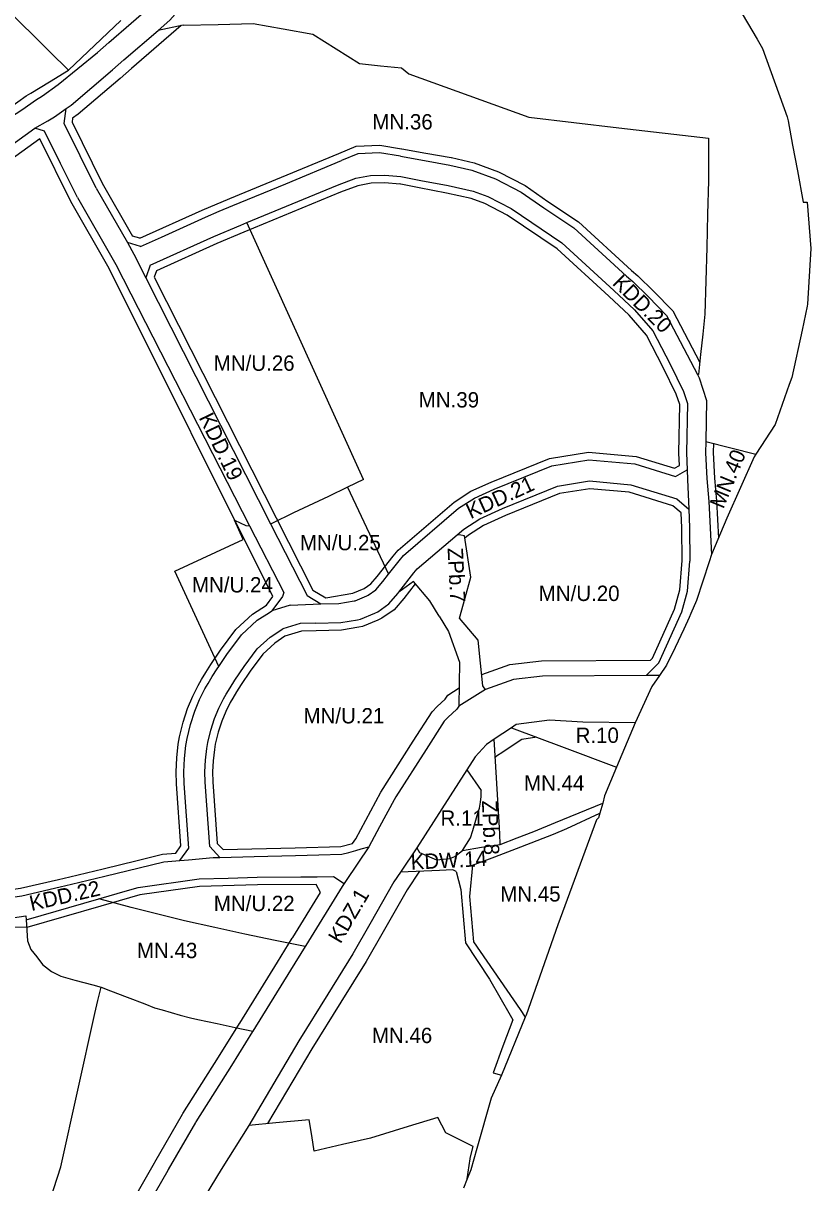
# Model space of a CAD drawing. Extents: x 7431080 to 7433370, y 5546450 to 5548428.
# Drawn here: x 7432959 to 7433370, y 5546903 to 5547508 of the extents above; entities that cross this region are included whole.
import ezdxf

# ---------------------------------------------------------------- set-up
doc = ezdxf.new("R2010")
doc.units = 0
for name, color, linetype in [('Linie Rozgraniczajace', 7, 'Continuous'), ('nieprzekraczalna linia zabudowy', 7, 'Continuous'), ('oznaczenia_przeznaczen', 7, 'Continuous')]:
    doc.layers.add(name, color=color, linetype=linetype)

msp = doc.modelspace()

# ---------------------------------------------------------------- linework, layer by layer
at = {"layer": 'Linie Rozgraniczajace'}
for p, q in [((7432982.62, 5547483.83), (7433010.04, 5547509.76)), ((7433042.48, 5547507.32), (7433029.48, 5547504.64)), ((7432987.32, 5547417.42), (7433007.33, 5547382.43)), ((7433020.31, 5547391.89), (7433013.41, 5547393.92)), ((7433025.39, 5547382.12), (7433023.1, 5547375.59)), ((7433315.46, 5547290.18), (7433341.59, 5547283.57)), ((7433128.31, 5547266.25), (7433149.82, 5547220.87)), ((7433186.4, 5547255.29), (7433194.75, 5547260.61)), ((7433189.09, 5547244.43), (7433197.43, 5547249.75)), ((7433095.07, 5547211.39), (7433094.41, 5547209.19)), ((7433094.41, 5547209.19), (7433088.77, 5547201.7)), ((7433098.38, 5547204.66), (7433088.77, 5547201.7)), ((7433103.72, 5547195.15), (7433094.52, 5547192.31)), ((7433111.84, 5547195.35), (7433103.72, 5547195.15)), ((7433190.6, 5547118.72), (7433198.09, 5547108.02)), ((7433240.83, 5547092.85), (7433261.68, 5547101.42)), ((7433242.87, 5547088.18), (7433260.05, 5547096.19)), ((7433185.13, 5547065.7), (7433187.55, 5547056.41)), ((7433193.62, 5547068.98), (7433192.08, 5547052.61)), ((7433187.55, 5547056.41), (7433189.98, 5547028.48)), ((7433192.08, 5547052.61), (7433194.1, 5547029.09)), ((7433189.98, 5547028.48), (7433202.57, 5547009.55)), ((7433194.1, 5547029.09), (7433218.46, 5546993.68)), ((7433202.57, 5547009.55), (7433213.32, 5546990.74)), ((7433218.46, 5546993.68), (7433221.14, 5546989.77)), ((7433204.34, 5546960.67), (7433208.74, 5546959.49))]:
    msp.add_line(p, q, dxfattribs=at)
for points in [[(7432965.39, 5547468.19), (7432969.04, 5547470.51), (7432977.24, 5547476.44), (7432997.87, 5547493.15), (7433003.78, 5547498.29), (7433027.14, 5547518.47), (7433035.83, 5547528.39), (7433046.28, 5547542.85)], [(7432928.37, 5547538.37), (7432936.78, 5547529.78), (7432945.54, 5547520.83), (7432954.3, 5547511.88), (7432958.8, 5547507.42), (7432963.3, 5547502.97), (7432972.96, 5547493.4), (7432982.62, 5547483.83)], [(7433324.78, 5547529.73), (7433342.34, 5547500), (7433345.12, 5547495.29), (7433358.01, 5547459.57), (7433358.41, 5547457.5), (7433360.75, 5547444.71), (7433363.33, 5547431.34), (7433366.28, 5547415.1), (7433368.36, 5547415.07), (7433370.28, 5547390.78), (7433368.48, 5547361.83), (7433368.41, 5547360.77), (7433365.71, 5547348.15), (7433360.41, 5547323.54), (7433358.96, 5547319.87), (7433351.64, 5547298.96), (7433341.59, 5547283.57), (7433340.67, 5547282.15), (7433326.35, 5547250.09), (7433318.44, 5547231.17), (7433317.17, 5547227.28), (7433310.58, 5547207.11), (7433307.59, 5547200.28), (7433306.7, 5547198.23), (7433303.99, 5547192.13), (7433299.53, 5547182.55), (7433295, 5547173.42), (7433291.25, 5547168), (7433287.26, 5547162.21), (7433278.53, 5547143.25), (7433268.86, 5547120.2), (7433262.55, 5547105.18), (7433261.68, 5547101.42), (7433260.05, 5547096.19), (7433259.5, 5547093.65), (7433258.46, 5547092.66), (7433238.12, 5547037.96), (7433221.68, 5546990.79), (7433221.14, 5546989.77), (7433208.74, 5546959.49), (7433203.4, 5546947.47), (7433195.88, 5546921.24), (7433192.74, 5546909.96), (7433190.89, 5546905.3), (7433189, 5546900.53)], [(7432971.88, 5547457.4), (7432975.45, 5547459.56), (7432981.41, 5547463.82), (7432984.03, 5547465.69), (7433005.69, 5547484.04), (7433011.64, 5547489.22), (7433029.48, 5547504.64), (7433035.61, 5547509.93), (7433045.71, 5547521.4)], [(7433042.48, 5547507.32), (7433060.79, 5547507.76), (7433079.1, 5547508.2), (7433094.72, 5547505.45), (7433110.33, 5547502.71), (7433122.51, 5547495.02), (7433134.69, 5547487.32), (7433145.67, 5547486.23), (7433156.64, 5547485.14), (7433158.49, 5547483.53), (7433160.34, 5547481.92), (7433191.72, 5547470.66), (7433223.1, 5547459.39)], [(7432951.44, 5547463.82), (7432956.27, 5547467.3), (7432960.65, 5547470.43), (7432962.98, 5547471.85), (7432972.8, 5547477.84), (7432982.62, 5547483.83)], [(7432951.94, 5547458.98), (7432958.79, 5547463.62), (7432965.39, 5547468.19)], [(7432997.16, 5547422.34), (7432980.46, 5547456.15), (7432981.41, 5547463.82)], [(7433223.1, 5547459.39), (7433269.95, 5547453.88), (7433316.81, 5547448.37), (7433316.85, 5547436.36), (7433316.86, 5547431.24), (7433316.88, 5547426.12), (7433316.41, 5547408.72), (7433315.94, 5547391.31), (7433315.47, 5547373.91), (7433315, 5547356.5), (7433314.44, 5547351.28), (7433313.88, 5547346.05), (7433312.75, 5547335.6), (7433311.61, 5547325.15), (7433311.03, 5547325.12)], [(7432944.76, 5547439.03), (7432965.08, 5547453.58), (7432971.88, 5547457.4)], [(7432987.32, 5547417.42), (7432978.52, 5547435.24), (7432970.21, 5547452.05), (7432965.08, 5547453.58)], [(7433155.99, 5547438.97), (7433145.07, 5547440.76), (7433133.81, 5547440.27), (7433125.29, 5547436.74)], [(7433020.31, 5547391.89), (7433031.18, 5547396.83), (7433054.16, 5547407.26), (7433061.32, 5547410.24), (7433068.47, 5547413.21), (7433096.16, 5547424.67), (7433125.29, 5547436.74)], [(7433155.99, 5547438.97), (7433168.53, 5547436.7), (7433181.73, 5547434.39)], [(7433181.73, 5547434.39), (7433193.29, 5547431.77), (7433205.67, 5547427.18), (7433219.03, 5547420.31), (7433230.8, 5547412.11), (7433234.55, 5547409.63), (7433246.52, 5547401.68), (7433274.03, 5547376.39), (7433277.32, 5547373.68), (7433285.34, 5547365.84), (7433294.87, 5547355.88), (7433311.03, 5547325.12), (7433311.97, 5547323.3), (7433315.83, 5547311.46), (7433315.46, 5547290.18), (7433315.36, 5547284.25), (7433315.96, 5547270.73), (7433317.1, 5547258.83), (7433318.44, 5547231.17)], [(7433025.39, 5547382.12), (7433058.55, 5547397.17), (7433072.69, 5547403.05), (7433075.78, 5547404.33), (7433123.2, 5547423.97), (7433132.74, 5547427.47), (7433140.3, 5547428.88), (7433147.82, 5547429.05), (7433156.13, 5547428.44)], [(7433156.13, 5547428.44), (7433166.62, 5547426.38), (7433180.87, 5547423.66)], [(7432997.16, 5547422.34), (7433013.41, 5547393.92), (7433016.86, 5547387.88)], [(7433180.87, 5547423.66), (7433194, 5547420.84), (7433201.63, 5547418.01), (7433213.83, 5547411.74), (7433240.35, 5547393.76), (7433267.46, 5547368.84), (7433278.23, 5547358.81), (7433287.74, 5547347.96), (7433296.82, 5547330.51), (7433303.74, 5547316.29), (7433305.81, 5547309.95), (7433305.36, 5547284.12), (7433305.74, 5547275.39), (7433305.97, 5547270.33), (7433306.53, 5547254.76), (7433306.88, 5547245.18), (7433307.16, 5547227.75)], [(7433136.72, 5547270.35), (7433075.78, 5547404.33)], [(7433016.86, 5547387.88), (7433023.1, 5547375.59), (7433088.23, 5547247.2), (7433107.22, 5547209.76)], [(7433007.33, 5547382.43), (7433077.26, 5547246.11), (7433095.07, 5547211.39)], [(7433194.75, 5547260.61), (7433204.98, 5547265.27), (7433234.98, 5547277.44), (7433254.35, 5547280.59), (7433278.38, 5547278.41), (7433299.64, 5547271.9), (7433305.74, 5547275.39)], [(7433136.72, 5547270.35), (7433128.31, 5547266.25), (7433118.45, 5547261.46), (7433100.09, 5547252.84), (7433088.91, 5547247.25), (7433088.29, 5547247.07)], [(7433197.43, 5547249.75), (7433209.33, 5547255.17), (7433237.97, 5547266.78), (7433254.74, 5547269.51), (7433276.25, 5547267.55), (7433300.26, 5547260.19), (7433306.53, 5547254.76)], [(7433098.38, 5547204.66), (7433114.48, 5547205.42), (7433123.86, 5547205.65), (7433131.89, 5547206.97), (7433132.33, 5547207.05), (7433138.43, 5547209.57), (7433139.07, 5547209.9), (7433143.17, 5547212.78), (7433146.87, 5547217.12), (7433149.82, 5547220.87), (7433155.27, 5547227.8), (7433157.61, 5547230.65), (7433186.4, 5547255.29)], [(7433061.12, 5547172.66), (7433038.23, 5547222.46), (7433073.92, 5547238.95), (7433069.34, 5547249.11), (7433072.38, 5547247.6), (7433075.33, 5547246.21), (7433077.26, 5547246.11)], [(7433111.84, 5547195.35), (7433124.8, 5547195.67), (7433133.55, 5547197.11), (7433135.12, 5547197.38), (7433142.61, 5547200.48), (7433144.23, 5547201.3), (7433149.96, 5547205.33), (7433154.61, 5547210.78), (7433155.16, 5547211.47), (7433163.06, 5547221.53), (7433164.78, 5547223.61), (7433185.67, 5547241.5), (7433189.09, 5547244.43)], [(7433192.82, 5547219.25), (7433189.52, 5547240.93), (7433187.46, 5547241.21), (7433185.67, 5547241.5)], [(7433284.23, 5547167.97), (7433291, 5547174.67), (7433302.95, 5547201.3), (7433305.87, 5547212.07), (7433307.16, 5547227.75)], [(7433176.2, 5547198.94), (7433171.37, 5547206.94), (7433162.74, 5547217.01), (7433155.16, 5547211.47)], [(7433200.36, 5547160.69), (7433199.69, 5547161.62), (7433199.02, 5547162.55), (7433197.83, 5547174.46), (7433196.63, 5547186.38), (7433191.7, 5547192.19), (7433186.76, 5547198), (7433189.79, 5547208.62), (7433192.82, 5547219.25)], [(7433107.22, 5547209.76), (7433114.48, 5547205.42)], [(7433040.86, 5547071.47), (7433045.44, 5547077.9), (7433043.13, 5547111.72), (7433042.93, 5547117.73), (7433043.19, 5547124.68), (7433043.98, 5547131.51), (7433044.62, 5547135.18), (7433046.37, 5547142.49), (7433048.62, 5547149.38), (7433051.16, 5547155.53), (7433053.89, 5547160.99), (7433055.53, 5547163.89), (7433057.77, 5547167.51), (7433060.37, 5547171.54), (7433061.12, 5547172.66), (7433065.32, 5547178.96), (7433072.99, 5547189.29), (7433081.23, 5547196.83), (7433087.55, 5547200.9), (7433088.77, 5547201.7)], [(7433176.2, 5547198.94), (7433181.02, 5547190.93), (7433186.9, 5547174.96), (7433186.67, 5547163.44), (7433186.44, 5547151.92)], [(7433061.69, 5547073.09), (7433056.41, 5547078.69), (7433054.12, 5547112.28), (7433053.93, 5547117.7), (7433054.17, 5547123.84), (7433054.87, 5547129.93), (7433055.4, 5547132.96), (7433056.96, 5547139.5), (7433058.94, 5547145.56), (7433061.18, 5547150.96), (7433063.6, 5547155.82), (7433064.99, 5547158.28), (7433067.07, 5547161.63), (7433069.57, 5547165.51), (7433074.32, 5547172.62), (7433081.2, 5547181.89), (7433087.97, 5547188.09), (7433094.52, 5547192.31)], [(7433291.25, 5547168), (7433284.23, 5547167.97), (7433230.18, 5547167.7), (7433215, 5547165.99), (7433200.36, 5547160.69), (7433186.44, 5547151.92), (7433185.49, 5547150.45), (7433180.79, 5547146.12), (7433178.84, 5547144.12), (7433169.46, 5547129.43), (7433153.62, 5547104.61), (7433152.65, 5547103.09), (7433145.09, 5547089.01), (7433139.48, 5547078.57), (7433127.62, 5547061.05), (7433126.62, 5547059.44), (7433125.62, 5547057.83), (7433106.54, 5547027.04), (7433106.26, 5547026.6), (7433098.63, 5547014.26), (7433078.95, 5546982.42), (7433078.83, 5546982.22), (7433067.71, 5546964.56), (7433049.18, 5546935.15), (7433048.95, 5546934.8), (7433034.77, 5546910.16), (7433034.52, 5546909.71), (7433022.02, 5546887.92)], [(7433278.53, 5547143.25), (7433251.17, 5547143.73), (7433233.76, 5547144.74), (7433216.46, 5547142.36), (7433214.01, 5547140.73), (7433204.97, 5547134.74), (7433200.92, 5547132.06), (7433200.68, 5547131.81), (7433194.97, 5547125.55), (7433190.6, 5547118.72), (7433164.59, 5547078.01), (7433156.08, 5547065.45), (7433152.64, 5547060.37), (7433140, 5547038.25), (7433131.19, 5547022.83), (7433118.1, 5547001.77), (7433102.9, 5546977.32), (7433076.81, 5546933.2), (7433062.31, 5546910.14), (7433048.7, 5546887.58)], [(7433214.01, 5547140.73), (7433241.44, 5547130.46), (7433268.86, 5547120.2)], [(7433208.14, 5547079.83), (7433207.83, 5547085.3), (7433207.47, 5547091.54), (7433204.97, 5547134.74)], [(7433188.47, 5547076.76), (7433190.49, 5547079.99), (7433192.51, 5547083.22), (7433193.73, 5547087.12), (7433196.14, 5547094.92), (7433197.34, 5547098.8), (7433197.75, 5547101.84), (7433198.15, 5547104.88), (7433198.09, 5547108.02)], [(7433198.26, 5547078.42), (7433208.14, 5547079.83), (7433217.03, 5547083.22), (7433225.6, 5547086.51), (7433237.04, 5547091.29), (7433240.83, 5547092.85)], [(7433193.62, 5547068.98), (7433205.24, 5547073.38), (7433218.81, 5547078.55), (7433227.4, 5547081.84), (7433235.96, 5547085.16), (7433242.87, 5547088.18)], [(7433001.64, 5547063.28), (7433019.52, 5547067.62), (7433032.48, 5547070.74), (7433040.86, 5547071.47), (7433045.32, 5547071.87), (7433058.15, 5547072.99), (7433061.69, 5547073.09), (7433079.69, 5547073.57), (7433101.22, 5547074.15), (7433113.31, 5547074.43), (7433125.4, 5547074.71), (7433129.07, 5547075.7), (7433132.74, 5547076.69), (7433135.55, 5547077.48), (7433139.48, 5547078.57)], [(7433164.59, 5547078.01), (7433165.92, 5547075.55), (7433174.8, 5547071.81), (7433181.83, 5547072.53), (7433184.32, 5547073.61), (7433188.47, 5547076.76), (7433198.26, 5547078.42)], [(7433185.13, 5547065.7), (7433183.34, 5547066.62), (7433176.42, 5547066.31), (7433156.08, 5547065.45)], [(7432850.53, 5546976.68), (7432855.97, 5546976.27), (7432858.91, 5546978.54), (7432870.7, 5547006.31), (7432879.21, 5547033.45), (7432892.92, 5547039.97), (7432897.83, 5547040.87), (7432906.82, 5547042.52), (7432929.63, 5547048.83), (7432935.6, 5547049.72), (7432958.38, 5547053.1), (7432978.31, 5547057.69), (7432984.23, 5547059.05), (7433001.64, 5547063.28)], [(7433013.49, 5547055.8), (7433019.02, 5547057.41), (7433050.83, 5547061.88), (7433066.06, 5547062.3), (7433081.28, 5547062.72), (7433103.99, 5547062.93), (7433112.45, 5547063.01), (7433120.98, 5547063.06), (7433126.62, 5547059.44)], [(7432891.92, 5547022.59), (7432896.75, 5547028.05), (7432936.06, 5547038.35), (7432947.55, 5547040.61), (7432960.49, 5547042.6), (7432960.58, 5547040.51), (7432998.53, 5547051.46), (7433013.49, 5547055.8)], [(7433106.26, 5547026.6), (7433090.54, 5547029.79), (7433074.83, 5547032.98), (7433059.03, 5547036.5), (7433043.22, 5547040.01), (7433029.32, 5547043.5), (7433015.41, 5547046.98), (7433006.97, 5547049.22), (7432998.53, 5547051.46)], [(7432960.58, 5547040.51), (7432961.3, 5547029.51), (7432963.07, 5547024.95), (7432966.11, 5547021.11), (7432969.15, 5547017.26), (7432973.81, 5547013.57), (7432978.63, 5547011.07), (7432986.03, 5547009.05), (7432995.36, 5547006.5), (7432999.69, 5547005.32), (7433004.63, 5547003.43), (7433013.39, 5547000.08), (7433022.46, 5546996.61), (7433027.63, 5546994.64), (7433031.53, 5546993.52), (7433036.25, 5546992.17), (7433040.96, 5546990.83), (7433046.36, 5546989.29), (7433050.29, 5546988.46), (7433055.29, 5546987.41), (7433060.28, 5546986.36), (7433069.62, 5546984.39), (7433078.95, 5546982.42)], [(7432928.81, 5546849.61), (7432932.61, 5546856.03), (7432937.75, 5546864.74), (7432942.9, 5546873.44), (7432951.57, 5546873.3), (7432960.23, 5546873.17), (7432964.71, 5546875.68), (7432969.18, 5546878.19), (7432970.36, 5546883.59), (7432971.53, 5546889), (7432975.11, 5546900.33), (7432978.69, 5546911.66), (7432996.45, 5546991.58), (7432998.07, 5546998.45), (7432999.69, 5547005.32)], [(7433213.32, 5546990.74), (7433214.68, 5546988.35), (7433209.51, 5546974.51), (7433204.34, 5546960.67)], [(7433193.98, 5546922.19), (7433187.75, 5546925.29), (7433179.63, 5546929.35), (7433177.56, 5546933.32), (7433175.49, 5546937.28), (7433159.99, 5546932.58), (7433140.36, 5546926.64), (7433125.68, 5546923.24), (7433111.01, 5546919.83), (7433109.66, 5546928.02), (7433108.32, 5546936.2), (7433090.99, 5546934.55), (7433076.81, 5546933.2)], [(7433190.89, 5546905.3), (7433192.39, 5546915.84), (7433192.44, 5546916.04), (7433192.45, 5546916.15), (7433193.98, 5546922.19)]]:
    msp.add_lwpolyline(points, dxfattribs=at)
at = {"layer": 'nieprzekraczalna linia zabudowy'}
for p, q in [((7432983.85, 5547415.43), (7432967.71, 5547448.08)), ((7433000.33, 5547424.86), (7433016.08, 5547397.3)), ((7433020.01, 5547396.15), (7433016.08, 5547397.3)), ((7433028.6, 5547379.18), (7433027.44, 5547375.88)), ((7433198.42, 5547168.5), (7433213.17, 5547173.83)), ((7433213.17, 5547173.83), (7433229.71, 5547175.7)), ((7433229.71, 5547175.7), (7433286.64, 5547175.98)), ((7433180.68, 5547157.75), (7433186.63, 5547161.5)), ((7433175.21, 5547151.86), (7433179.32, 5547155.65)), ((7433179.32, 5547155.65), (7433180.68, 5547157.75)), ((7433162.72, 5547133.73), (7433172.54, 5547149.12)), ((7433172.54, 5547149.12), (7433175.21, 5547151.86)), ((7433145.74, 5547107.14), (7433162.72, 5547133.73)), ((7433132.64, 5547082.73), (7433145.74, 5547107.14)), ((7433131.04, 5547080.38), (7433132.64, 5547082.73)), ((7433099.77, 5547031.29), (7433114.32, 5547054.79)), ((7433091.83, 5547018.47), (7433099.48, 5547030.85)), ((7433099.48, 5547030.85), (7433099.77, 5547031.29)), ((7433072.12, 5546986.58), (7433091.83, 5547018.47)), ((7433060.94, 5546968.82), (7433072.01, 5546986.41)), ((7433072.01, 5546986.41), (7433072.12, 5546986.58)), ((7433042.45, 5546939.48), (7433060.94, 5546968.82)), ((7433027.81, 5546914.1), (7433042.13, 5546939)), ((7433042.13, 5546939), (7433042.45, 5546939.48)), ((7433014.97, 5546891.7), (7433027.55, 5546913.64)), ((7433027.55, 5546913.64), (7433027.81, 5546914.1))]:
    msp.add_line(p, q, dxfattribs=at)
for points in [[(7433041.55, 5547507.13), (7433015.57, 5547484.69), (7433009.6, 5547479.49), (7432987.72, 5547460.95), (7432984.83, 5547458.88)], [(7432984.83, 5547458.88), (7432984.57, 5547456.85), (7433000.33, 5547424.86)], [(7432967.71, 5547448.08), (7432941.31, 5547429.18)], [(7433020.01, 5547396.15), (7433052.56, 5547410.93), (7433066.94, 5547416.9), (7433123.76, 5547440.43)], [(7433123.76, 5547440.43), (7433132.93, 5547444.24), (7433145.31, 5547444.78), (7433156.63, 5547442.92)], [(7433156.7, 5547442.91), (7433169.23, 5547440.64), (7433182.42, 5547438.33)], [(7433182.61, 5547438.29), (7433194.44, 5547435.61), (7433207.29, 5547430.84), (7433221.1, 5547423.75), (7433233.05, 5547415.42), (7433248.99, 5547404.83), (7433276.66, 5547379.41), (7433279.99, 5547376.66), (7433288.18, 5547368.65), (7433298.15, 5547358.24), (7433312.28, 5547331.34)], [(7433155.84, 5547424.45), (7433147.72, 5547425.04), (7433140.72, 5547424.89), (7433133.81, 5547423.6), (7433124.66, 5547420.24), (7433074.22, 5547399.36), (7433060.14, 5547393.5), (7433028.6, 5547379.18)], [(7433180.12, 5547419.73), (7433165.86, 5547422.45), (7433155.36, 5547424.51)], [(7433089.45, 5547209.25), (7433003.86, 5547380.44), (7432983.85, 5547415.43)], [(7433301.64, 5547277.65), (7433301.35, 5547284.06), (7433301.8, 5547309.35), (7433300.02, 5547314.79), (7433293.25, 5547328.71), (7433284.41, 5547345.68), (7433275.35, 5547356.02), (7433264.75, 5547365.91), (7433237.86, 5547390.61), (7433211.78, 5547408.29), (7433200.02, 5547414.34), (7433192.88, 5547416.99), (7433180.03, 5547419.74)], [(7433027.44, 5547375.88), (7433110.27, 5547212.6)], [(7433319.45, 5547289.17), (7433319.36, 5547284.3), (7433319.95, 5547271.01), (7433321.09, 5547259.12), (7433322.03, 5547239.75)], [(7433154.75, 5547233.46), (7433184.01, 5547258.51), (7433192.83, 5547264.14), (7433203.4, 5547268.95), (7433233.9, 5547281.32), (7433254.21, 5547284.62), (7433279.15, 5547282.35), (7433299.16, 5547276.23), (7433301.64, 5547277.65)], [(7433302.6, 5547252.87), (7433298.28, 5547256.61), (7433275.47, 5547263.61), (7433254.89, 5547265.48), (7433239.05, 5547262.91), (7433210.91, 5547251.49), (7433199.35, 5547246.23), (7433191.47, 5547241.2), (7433189.71, 5547239.69)], [(7433303.16, 5547227.69), (7433302.88, 5547245.07), (7433302.6, 5547252.87)], [(7433110.27, 5547212.6), (7433117, 5547208.57), (7433131.21, 5547210.91), (7433137, 5547213.33), (7433140.46, 5547215.76), (7433143.78, 5547219.65), (7433152.15, 5547230.31), (7433154.75, 5547233.46)], [(7433286.64, 5547175.98), (7433287.66, 5547176.99), (7433299.18, 5547202.65), (7433301.91, 5547212.76), (7433303.17, 5547228.08)], [(7433163.71, 5547215.88), (7433157.71, 5547208.24), (7433152.67, 5547202.35), (7433146.29, 5547197.86), (7433144.28, 5547196.84), (7433136.24, 5547193.51), (7433134.21, 5547193.17), (7433125.18, 5547191.68), (7433111.94, 5547191.35), (7433104.37, 5547191.16), (7433095.7, 5547188.49), (7433090.42, 5547184.91), (7433084.18, 5547179.2), (7433077.59, 5547170.32), (7433072.91, 5547163.32), (7433070.45, 5547159.49), (7433068.43, 5547156.24), (7433067.13, 5547153.95), (7433064.82, 5547149.3), (7433062.7, 5547144.17), (7433060.81, 5547138.41), (7433059.32, 5547132.15), (7433058.84, 5547129.36), (7433058.16, 5547123.53), (7433057.94, 5547117.69), (7433058.11, 5547112.48), (7433060.3, 5547080.39), (7433063.38, 5547077.13)], [(7433038.67, 5547075.3), (7433041.35, 5547079.05), (7433039.14, 5547111.51), (7433038.92, 5547117.74), (7433039.2, 5547124.99), (7433040.02, 5547132.09), (7433040.71, 5547135.99), (7433042.51, 5547143.58), (7433044.86, 5547150.77), (7433047.52, 5547157.19), (7433050.35, 5547162.87), (7433052.08, 5547165.93), (7433054.39, 5547169.65), (7433057.03, 5547173.74), (7433062.05, 5547181.26), (7433070.01, 5547191.98), (7433078.78, 5547200.01), (7433086.01, 5547204.67), (7433089.45, 5547209.25)], [(7433227.26, 5547135.77), (7433219.37, 5547134.68), (7433218.44, 5547134.07), (7433209.39, 5547128.07), (7433206.13, 5547125.92), (7433205.52, 5547125.24)], [(7433063.38, 5547077.13), (7433101.12, 5547078.15), (7433124.82, 5547078.7), (7433131.04, 5547080.38)], [(7433000.7, 5547067.17), (7433018.58, 5547071.51), (7433031.83, 5547074.7), (7433038.67, 5547075.3)], [(7432852.29, 5546985), (7432857.14, 5546984.6), (7432866.94, 5547007.69), (7432875.92, 5547036.31), (7432891.68, 5547043.81), (7432897.11, 5547044.8), (7432905.92, 5547046.42), (7432928.8, 5547052.75), (7432935.01, 5547053.68), (7432957.64, 5547057.03), (7432977.41, 5547061.59), (7432983.31, 5547062.94), (7433000.7, 5547067.17)], [(7433166.03, 5547065.87), (7433159.43, 5547056.14), (7433146.95, 5547034.28), (7433138.06, 5547018.73), (7433124.89, 5546997.55), (7433109.74, 5546973.17), (7433086.66, 5546934.14)], [(7433114.32, 5547054.79), (7433111.96, 5547059), (7433081.35, 5547058.72), (7433051.17, 5547057.89), (7433019.86, 5547053.49), (7433014.6, 5547051.96)], [(7433014.6, 5547051.96), (7432999.64, 5547047.62), (7432960.85, 5547036.42)], [(7432960.85, 5547036.42), (7432948.24, 5547036.67), (7432936.95, 5547034.44), (7432898.94, 5547024.49), (7432894.92, 5547019.94)]]:
    msp.add_lwpolyline(points, dxfattribs=at)

# ---------------------------------------------------------------- texts
at = {"layer": 'oznaczenia_przeznaczen'}
for s, p in [('MN.36', (7433141.35, 5547452.97)), ('MN/U.26', (7433058.53, 5547327.02)), ('MN.39', (7433165.56, 5547307.88)), ('MN/U.25', (7433103.54, 5547233.36)), ('MN/U.24', (7433047.16, 5547211.34)), ('MN/U.20', (7433228.21, 5547206.89)), ('MN/U.21', (7433105.38, 5547143)), ('R.10', (7433247.46, 5547132.82)), ('MN.44', (7433220.56, 5547107.9)), ('R.11', (7433176.92, 5547089.61)), ('MN/U.22', (7433058.55, 5547045.07)), ('MN.45', (7433208.11, 5547050.06)), ('MN.43', (7433018.42, 5547020.51)), ('MN.46', (7433141.09, 5546976.18))]:
    msp.add_text(s, height=8, dxfattribs=at).set_placement(p)
for s, rotation, p in [('KDD.20', 315.50064, (7433266.22, 5547372.3)), ('KDD.19', 295.8335, (7433050.57, 5547302.62)), ('MN.40', 67.63996, (7433324.59, 5547254.58)), ('KDD.21', 24.64217, (7433192.65, 5547249.53)), ('ZPb.7', 272.78193, (7433180.62, 5547234.5)), ('ZPb.8', 272.36218, (7433198.54, 5547102.72)), ('KDW.14', 2.85878, (7433161.56, 5547066.64)), ('KDD.22', 12.83023, (7432963.33, 5547045.07)), ('KDZ.1', 59.4754, (7433124.68, 5547027.62))]:
    msp.add_text(s, height=8, rotation=rotation, dxfattribs=at).set_placement(p)

doc.saveas('drawing.dxf')
